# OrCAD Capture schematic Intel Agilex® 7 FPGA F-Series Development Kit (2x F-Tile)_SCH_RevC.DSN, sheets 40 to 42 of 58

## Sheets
40 PG43 INPUT POWER HSC: size C
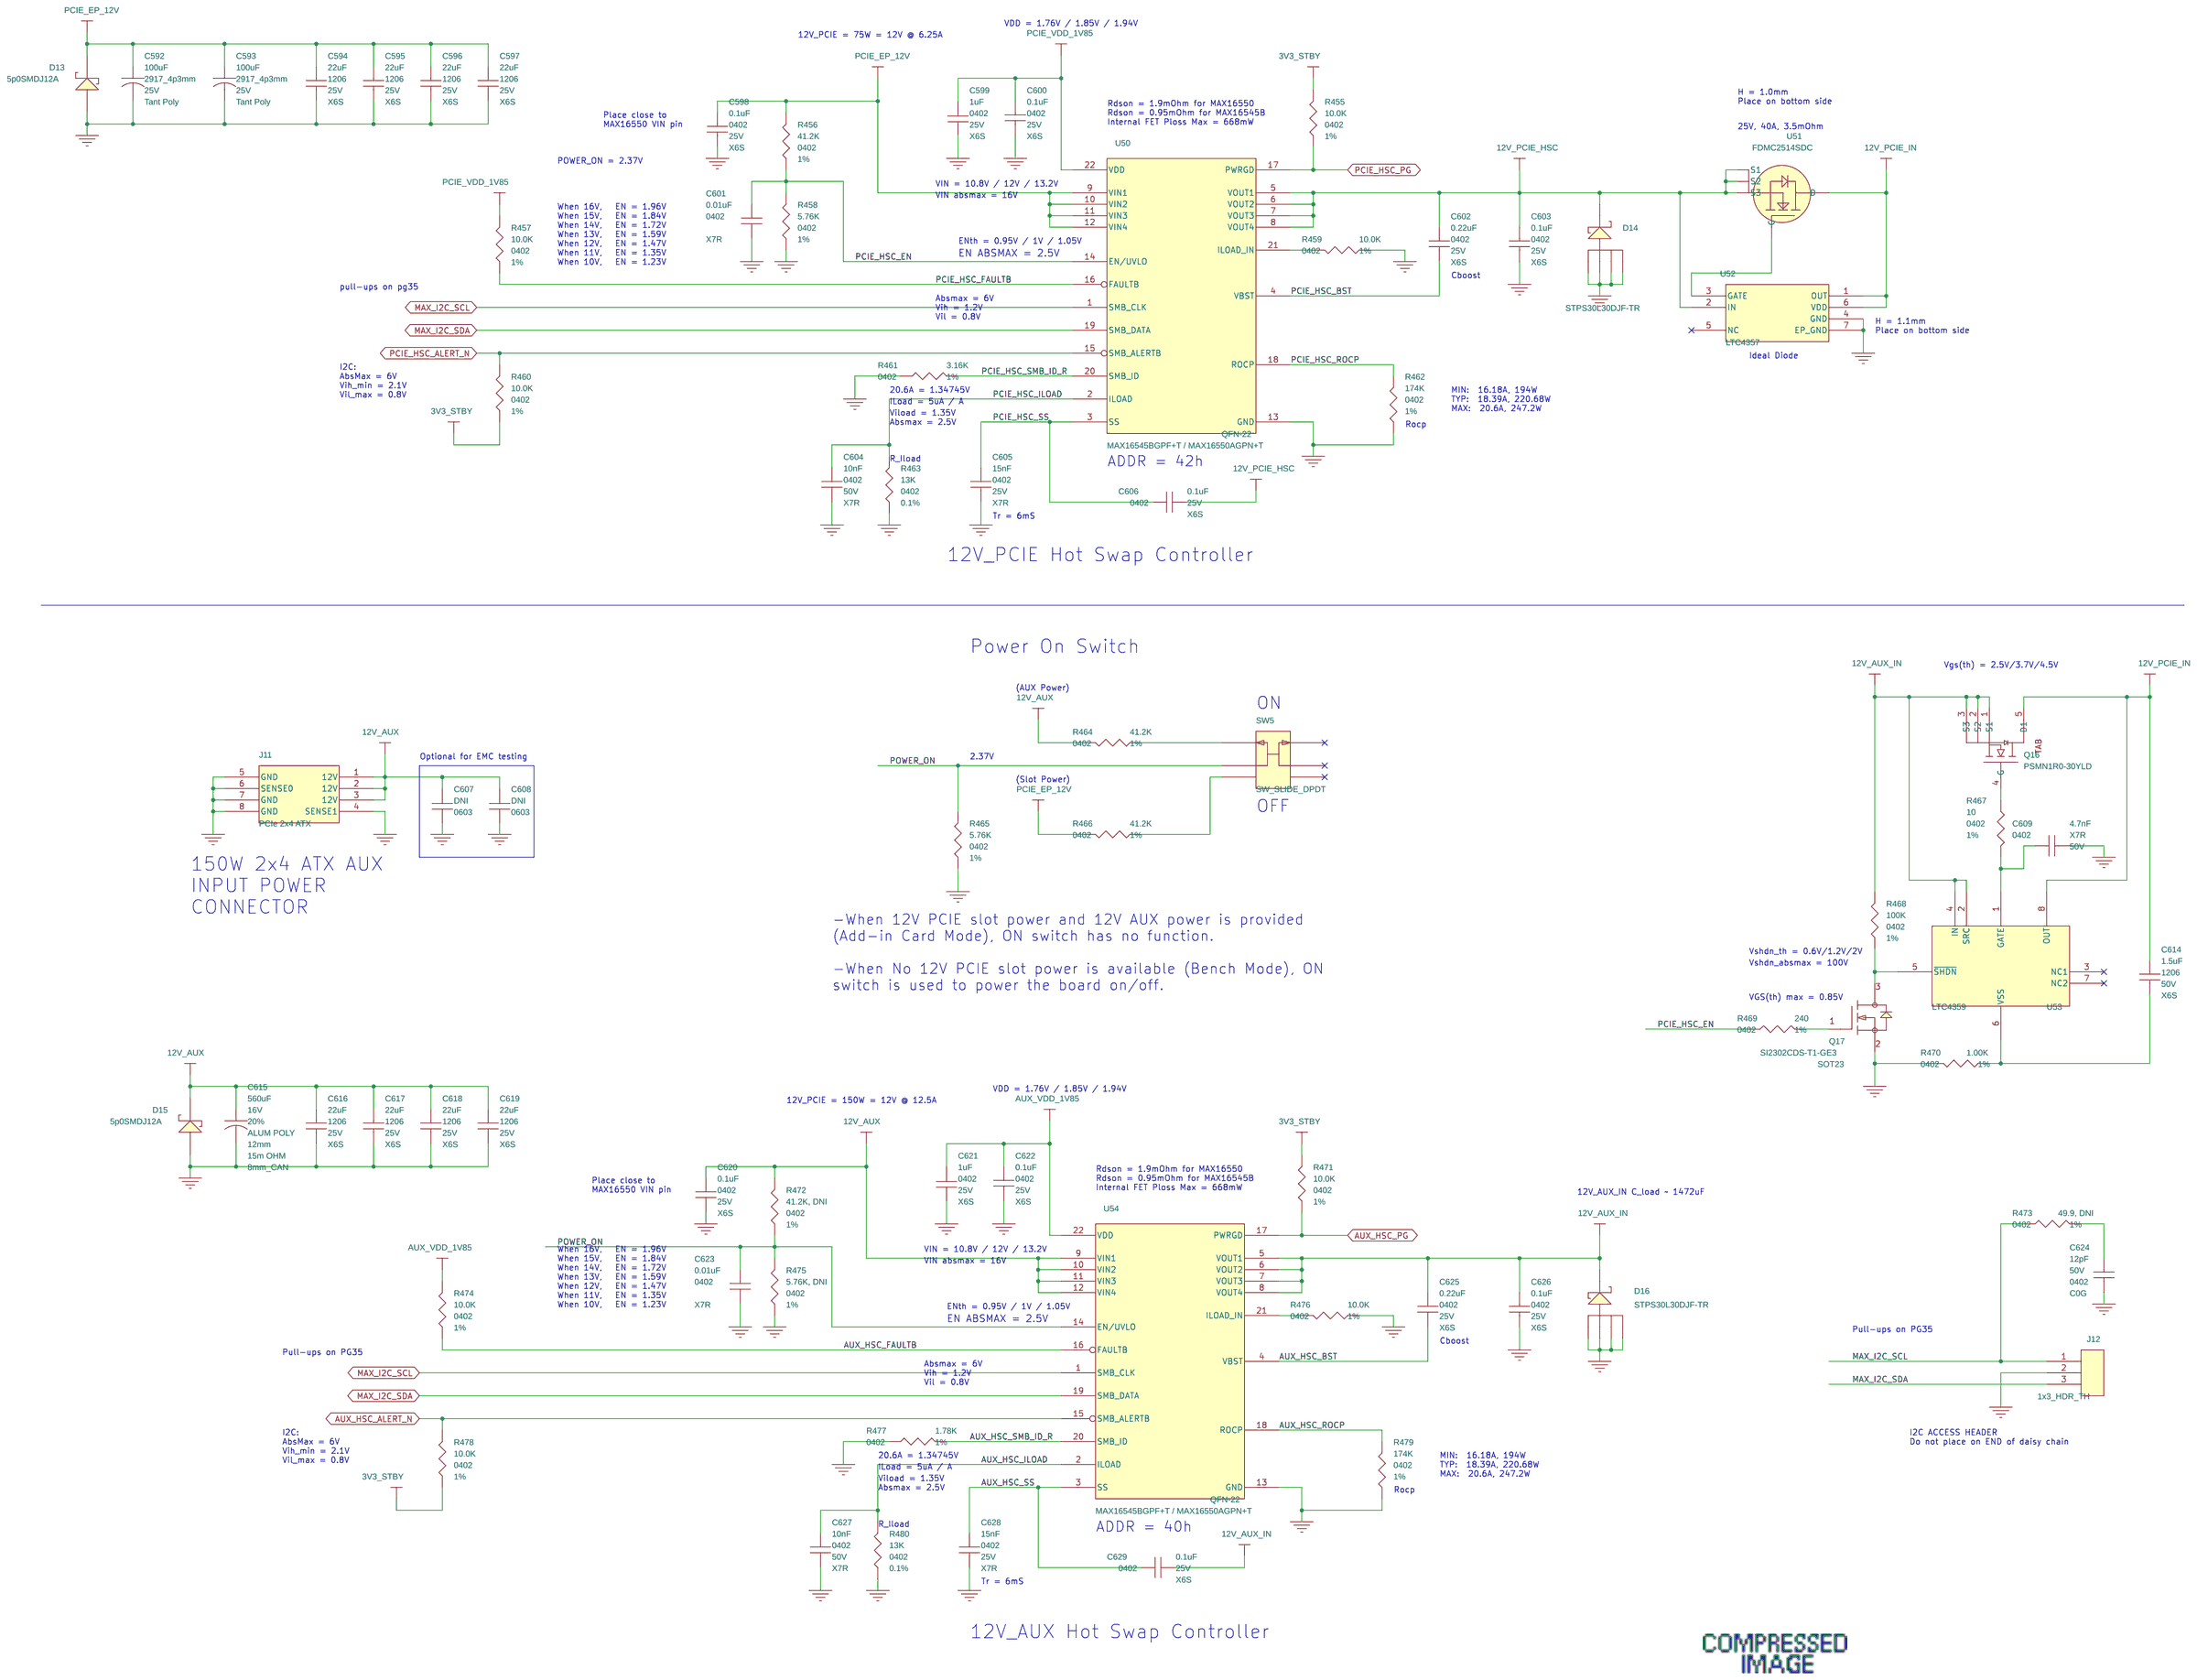
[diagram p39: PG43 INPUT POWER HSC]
41 PG45 3V3_STBY, 3V3_SYS: size C
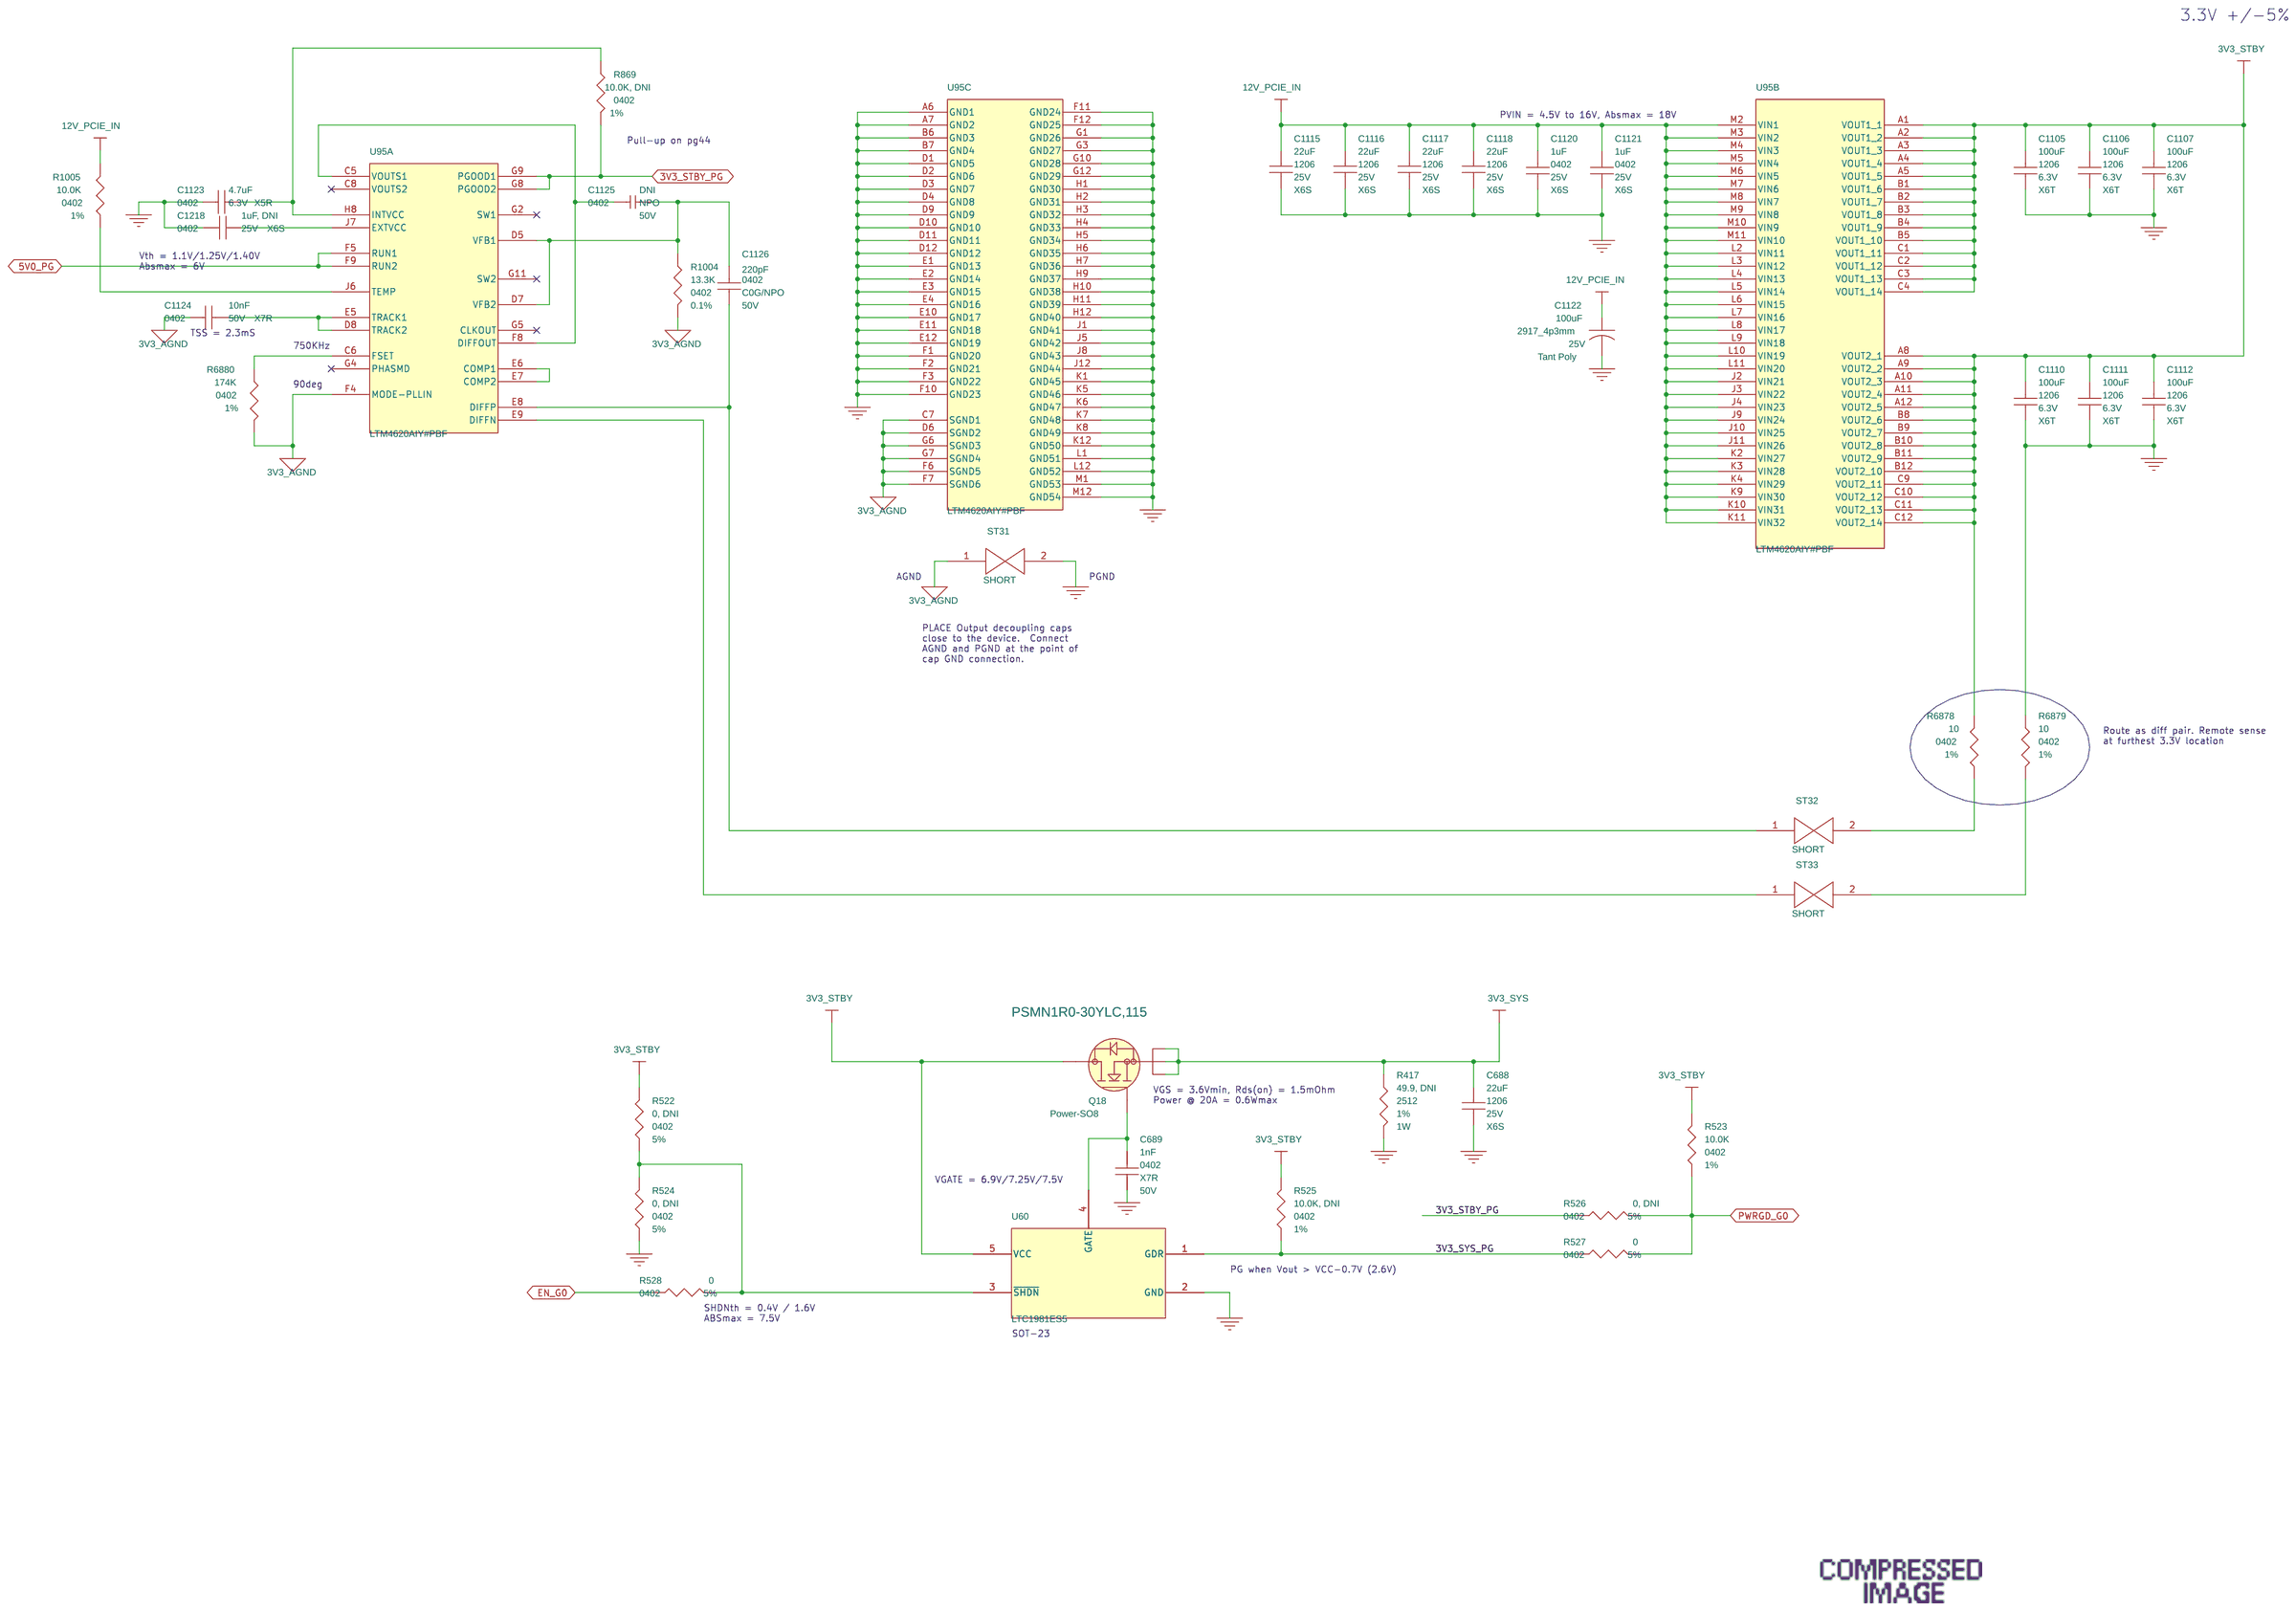
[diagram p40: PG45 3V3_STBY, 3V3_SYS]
42 PG46 VCC Controller: size C
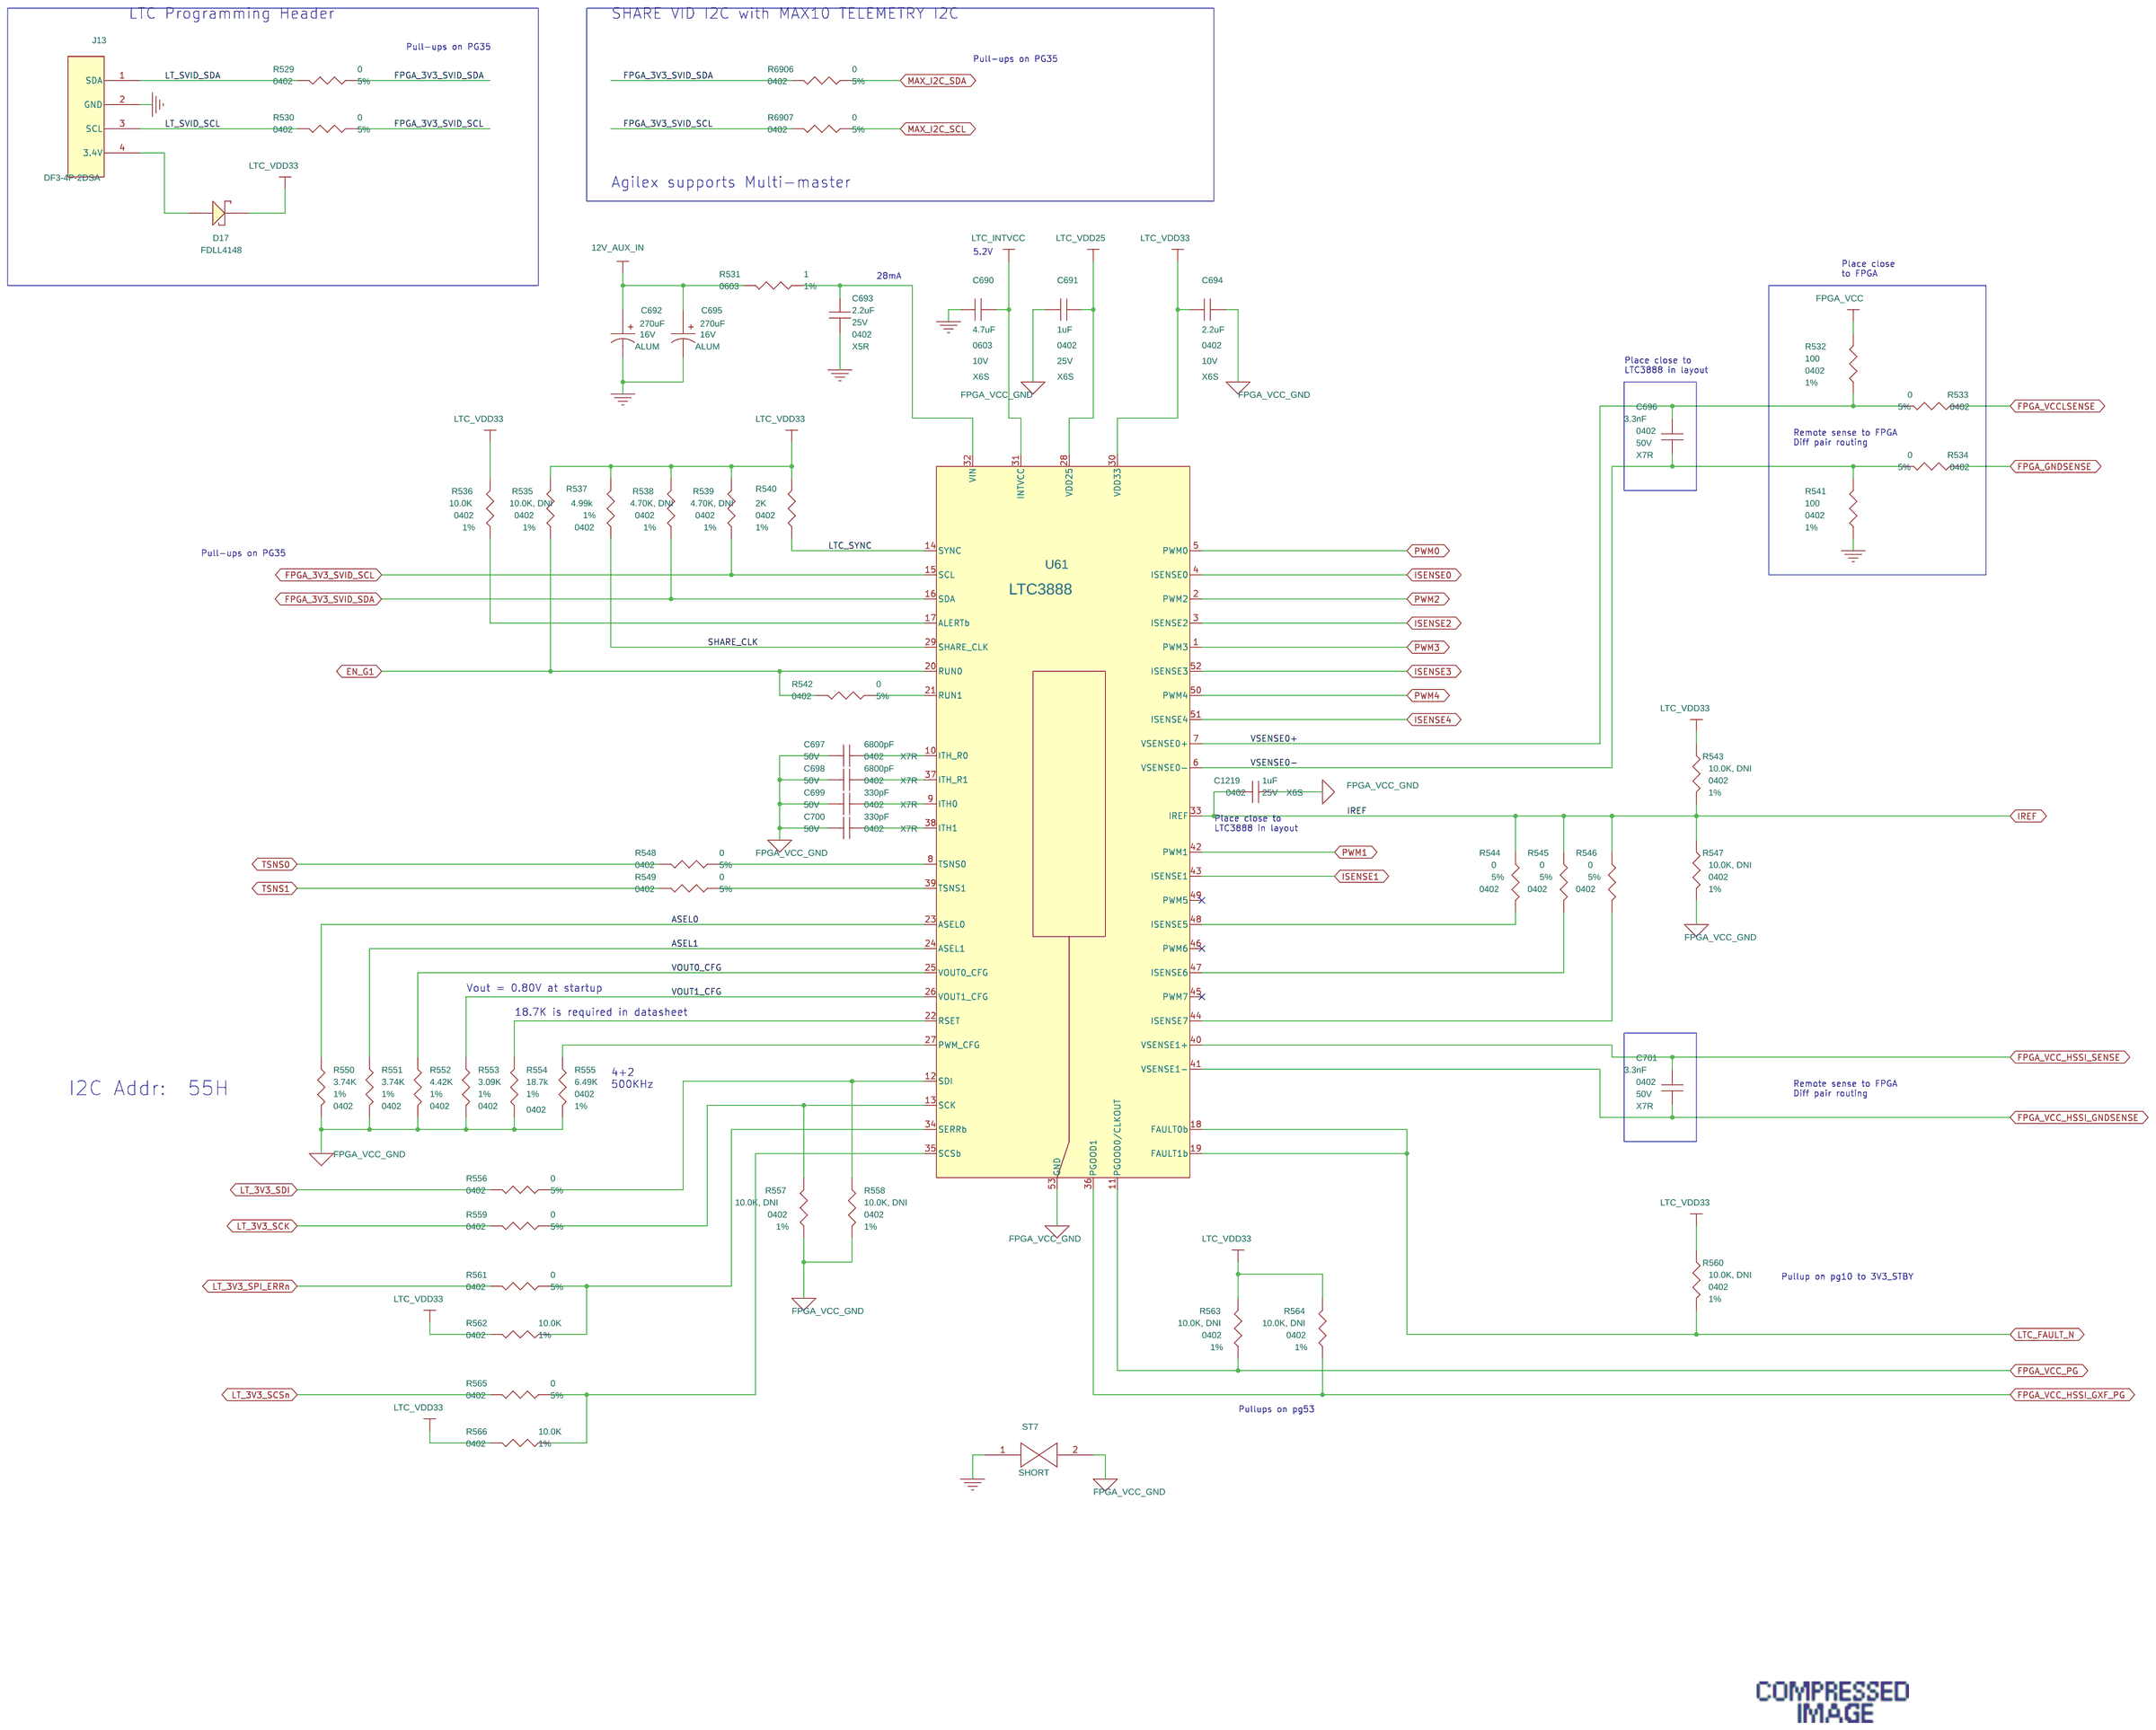
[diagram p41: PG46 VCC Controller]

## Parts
sheet PG43 INPUT POWER HSC
C592  100uF  [2917_4p3mm]
C593  100uF  [2917_4p3mm]
C594  22uF  [1206]
C595  22uF  [1206]
C596  22uF  [1206]
C597  22uF  [1206]
C598  0.1uF  [0402]
C599  1uF  [0402]
C600  0.1uF  [0402]
C601  0.01uF  [0402]
C602  0.22uF  [0402]
C603  0.1uF  [0402]
C604  10nF  [0402]
C605  15nF  [0402]
C606  0.1uF  [0402]
C607  DNI  [0603]
C608  DNI  [0603]
C609  4.7nF  [0402]
C614  1.5uF  [1206]
C615  560uF  [8mm_CAN]
C616  22uF  [1206]
C617  22uF  [1206]
C618  22uF  [1206]
C619  22uF  [1206]
C620  0.1uF  [0402]
C621  1uF  [0402]
C622  0.1uF  [0402]
C623  0.01uF  [0402]
C624  12pF  [0402]
C625  0.22uF  [0402]
C626  0.1uF  [0402]
C627  10nF  [0402]
C628  15nF  [0402]
C629  0.1uF  [0402]
D13  5p0SMDJ12A  [TVS_5p0SMDJ12A]
D14  STPS30L30DJF-TR  [PowerFLAT_5x6]
D15  5p0SMDJ12A  [TVS_5p0SMDJ12A]
D16  STPS30L30DJF-TR  [PowerFLAT_5x6]
J11  PCIe 2x4 ATX  [MOLEX_455860005]
J12  1x3_HDR_TH  [1x3_HDR_TH]
Q16  PSMN1R0-30YLD  [NFET_PSMN1R0-30YLD]
Q17  SI2302CDS-T1-GE3  [SOT23]
R455  10.0K  [0402]
R456  41.2K  [0402]
R457  10.0K  [0402]
R458  5.76K  [0402]
R459  10.0K  [0402]
R460  10.0K  [0402]
R461  3.16K  [0402]
R462  174K  [0402]
R463  13K  [0402]
R464  41.2K  [0402]
R465  5.76K  [0402]
R466  41.2K  [0402]
R467  10  [0402]
R468  100K  [0402]
R469  240  [0402]
R470  1.00K  [0402]
R471  10.0K  [0402]
R472  41.2K, DNI  [0402]
R473  49.9, DNI  [0402]
R474  10.0K  [0402]
R475  5.76K, DNI  [0402]
R476  10.0K  [0402]
R477  1.78K  [0402]
R478  10.0K  [0402]
R479  174K  [0402]
R480  13K  [0402]
SW5  SW_SLIDE_DPDT  [EG2207]
U50  MAX16545BGPF+T / MAX16550AGPN+T  [QFN-22]
U51  FDMC2514SDC  [FDMC8878_VER2]
U52  LTC4357  [dfn6_epad]
U53  LTC4359  [MSOP-8]
U54  MAX16545BGPF+T / MAX16550AGPN+T  [QFN-22]
sheet PG45 3V3_STBY, 3V3_SYS
C688  22uF  [1206]
C689  1nF  [0402]
C1105  100uF  [1206]
C1106  100uF  [1206]
C1107  100uF  [1206]
C1110  100uF  [1206]
C1111  100uF  [1206]
C1112  100uF  [1206]
C1115  22uF  [1206]
C1116  22uF  [1206]
C1117  22uF  [1206]
C1118  22uF  [1206]
C1120  1uF  [0402]
C1121  1uF  [0402]
C1122  100uF  [2917_4p3mm]
C1123  4.7uF  [0402]
C1124  10nF  [0402]
C1125  DNI  [0402]
C1126  220pF  [0402]
C1218  1uF, DNI  [0402]
Q18  PSMN1R0-30YLC,115  [Power-SO8]
R417  49.9, DNI  [2512]
R522  0, DNI  [0402]
R523  10.0K  [0402]
R524  0, DNI  [0402]
R525  10.0K, DNI  [0402]
R526  0, DNI  [0402]
R527  0  [0402]
R528  0  [0402]
R869  10.0K, DNI  [0402]
R1004  13.3K  [0402]
R1005  10.0K  [0402]
R6878  10  [0402]
R6879  10  [0402]
R6880  174K  [0402]
ST31  SHORT  [SHORT]
ST32  SHORT  [SHORT]
ST33  SHORT  [SHORT]
U60  LTC1981ES5  [LTC1981ES5_SOT23]
U95  LTM4620AIY#PBF  [BGA-144_REVERSE]  (sections A,B,C)
sheet PG46 VCC Controller
C690  4.7uF  [0603]
C691  1uF  [0402]
C692  270uF  [PANASONIC_SVPC_8X12]
C693  2.2uF  [0402]
C694  2.2uF  [0402]
C695  270uF  [PANASONIC_SVPC_8X12]
C696  3.3nF  [0402]
C697  6800pF  [0402]
C698  6800pF  [0402]
C699  330pF  [0402]
C700  330pF  [0402]
C701  3.3nF  [0402]
C1219  1uF  [0402]
D17  FDLL4148  [SOD-80]
J13  DF3-4P-2DSA  [DF3-4P-2DSA_01]
R529  0  [0402]
R530  0  [0402]
R531  1  [0603]
R532  100  [0402]
R533  0  [0402]
R534  0  [0402]
R535  10.0K, DNI  [0402]
R536  10.0K  [0402]
R537  4.99k  [0402]
R538  4.70K, DNI  [0402]
R539  4.70K, DNI  [0402]
R540  2K  [0402]
R541  100  [0402]
R542  0  [0402]
R543  10.0K, DNI  [0402]
R544  0  [0402]
R545  0  [0402]
R546  0  [0402]
R547  10.0K, DNI  [0402]
R548  0  [0402]
R549  0  [0402]
R550  3.74K  [0402]
R551  3.74K  [0402]
R552  4.42K  [0402]
R553  3.09K  [0402]
R554  18.7k  [0402]
R555  6.49K  [0402]
R556  0  [0402]
R557  10.0K, DNI  [0402]
R558  10.0K, DNI  [0402]
R559  0  [0402]
R560  10.0K, DNI  [0402]
R561  0  [0402]
R562  10.0K  [0402]
R563  10.0K, DNI  [0402]
R564  10.0K, DNI  [0402]
R565  0  [0402]
R566  10.0K  [0402]
R6906  0  [0402]
R6907  0  [0402]
ST7  SHORT  [SHORT]
U61  LTC3888  [LTC-UHG-52-1550]

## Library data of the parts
C592 C593 C1122 = PCAP: CAP TANTALUM 100UF 25V 2917; AGILE_LINK: http://sj-agile9app/Agile/PLMServlet?action=OpenEmailObject&classid=10000&objid=257237054; Item Num: H48376-001; LIFECYCLE_PHASE: Active; Lead Free Status: Lead Free; MFR_LIFECYCLE: Active; Manufacturer: Kemet; Manufacturer Part Num: T521X107M025ATE060; Num Pins: 2; PART_SUBCLASS: CAPACITORS; RATED_VOLTAGE: 25V; RoHS Compliant: RoHS Compliant; TOLERANCE: 20%; Type: Tant Poly
C594-C597 C616-C619 C688 C1115-C1118 = CAP: CAP CER 22UF 25V X6S 1206; AGILE_LINK: http://sj-agile9app/Agile/PLMServlet?action=OpenEmailObject&classid=10000&objid=257560276; Item Num: H65936-001; LIFECYCLE_PHASE: Active; Lead Free Status: Lead Free; MFR_LIFECYCLE: Active; Manufacturer: Murata; Manufacturer Part Num: GRM31CC81E226KE11L; Num Pins: 2; PART_SUBCLASS: CAPACITORS; RATED_VOLTAGE: 25V; RoHS Compliant: RoHS Compliant; TOLERANCE: 10%; Thermal Coefficient: X6S
C598 C600 C603 C606 C620 C622 C626 C629 = CAP: CAP CER 0.1UF 25V X6S 0402; Dielectric: X6S; IPN: K19434-001; Item Num: K19434-001; LIFECYCLE_PHASE: Active; Lead Free Status: Lead Free; MFR_LIFECYCLE: Active; Manufacturer: Murata; Manufacturer Part Num: GRM155C81E104KA12D; Num Pins: 2; PART_SUBCLASS: CAPACITORS; Part Class: CAPACITORS; RATED_VOLTAGE: 25V; RoHS Compliant: RoHS Compliant; Temperature Coefficient: X6S; Tolerance: 10%
C599 C621 C691 C1120 C1121 C1218 C1219 = CAP: CAP CER 1UF 25V X6S 0402; Item Num: H81594-001; Lead Free Status: Yes; Manufacturer: Murata; Manufacturer Part Num: GRM155C81E105KE11D; Num Pins: 2; Part Class: CAPACITORS; RATED_VOLTAGE: 25V; RoHS Compliant: Yes; Temperature Coefficient: X6S
C601 C623 = CAP: CAP, CER .01UF 16V X7R 0402; Item Num: A36096-008; Lead Free Status: Yes; Manufacturer: Murata; Manufacturer Part Num: GRM155R71E103KA01D; Manufacturer's Part No.: GRM155R71C103KA01D; Num Pins: 2; Part Class: CAPACITORS; RoHS Compliant: Yes; TOLERANCE: 10%; Temperature Coefficient: X7R; Voltage: 16V
C602 C625 = CAP: CAP CER 0.22UF 25V X6S 0402; CAPACITANCE: 0.1uF; Dielectric: X6S; Item Num: K19428-001; LIFECYCLE_PHASE: Active; Lead Free Status: Lead Free; Manufacturer: Murata; Manufacturer Part Num: GRT155C81E224KE01D; Num Pins: 2; Part Class: CAPACITORS; RATED_VOLTAGE: 25V; RoHS Compliant: RoHS Compliant; Tolerance: 10%
C604 C627 = CAP: CAP - CER, 10NF, 50V, +/-10%, X7R, 0402 SMD; Dielectric: X7R; Item Num: H61346-001; LIFECYCLE_PHASE: Active; Lead Free Status: Lead Free; Manufacturer: Murata; Manufacturer Part Num: GRM155R71H103KA88D; Num Pins: 2; Part Class: CAPACITORS; RATED_VOLTAGE: 50V; RoHS Compliant: RoHS Compliant; Temperature Coefficient: X7R; Tolerance: 10%; Voltage: 50V
C605 C628 = CAP: CAP CER 0.015UF 25V X7R 0402; CAPACITANCE: 0.015uF; Dielectric: X7R; Item Num: K28300-001; LIFECYCLE_PHASE: Active; Lead Free Status: Lead Free; Manufacturer: Murata; Manufacturer Part Num: GRM155R71E153KA61D; Num Pins: 2; Part Class: CAPACITORS; RATED_VOLTAGE: 25V; RoHS Compliant: RoHS Compliant; Tolerance: 10%
C607 C608 = CAP: DNI Place Holder; AGILE_LINK: http://sj-agile9app/Agile/PLMServlet?action=OpenEmailObject&classid=10000&objid=257560276; Item Num: XXXXXX-XXX; LIFECYCLE_PHASE: Active; Lead Free Status: Not Lead Free; MFR_LIFECYCLE: Active; Num Pins: 2; PART_SUBCLASS: CAPACITORS; RoHS Compliant: RoHS Compliant
C609 = CAP: CAP - CER 4700PF 50V 10% X7R 0402; AGILE_LINK: http://sj-agile9app/Agile/PLMServlet?action=OpenEmailObject&classid=10000&objid=256989767; Item Num: G24897-001; LIFECYCLE_PHASE: Active; Lead Free Status: Lead Free; MFR_LIFECYCLE: Active; Manufacturer: Murata; Manufacturer Part Num: GRM155R71H472KA01D; Num Pins: 2; PACKAGING: Tape & Reel (TR); PART_SUBCLASS: CAPACITORS; RATED_VOLTAGE: 50V; RoHS Compliant: RoHS Compliant; Supplier Part Num: GRM155R71H472KA01D; TOLERANCE: 10%; Temperature Coefficient: X7R
C614 = CAP: CAP CER 1.5UF 50V X6S 1206; Dielectric: X6S; Item Num: K19472-001; LIFECYCLE_PHASE: Active; Lead Free Status: Lead Free; Manufacturer: Murata; Manufacturer Part Num: GRT31CC81H155KE01L; Num Pins: 2; Part Class: CAPACITORS; RATED_VOLTAGE: 50V; RoHS Compliant: RoHS Compliant; Tolerance: 10%
C615 = PCAP: 560µF ±20% 16V Aluminum Polymer Capacitor Radial, Can - SMD 14 mOhm 5000 Hrs @ 105°C; AGILE_LINK: http://sj-agile9app/Agile/PLMServlet?action=OpenEmailObject&classid=10000&objid=257237054; ESR: 15m OHM; Height: 12mm; Item Num: K22159-001; LIFECYCLE_PHASE: Active; Lead Free Status: Lead Free; MFR_LIFECYCLE: Active; Manufacturer: Panasonic; Manufacturer Part Num: 16SVPF560M; Num Pins: 2; PART_SUBCLASS: CAPACITORS; RATED_VOLTAGE: 16V; RoHS Compliant: RoHS Compliant; TOLERANCE: 20%; TYPE: ALUM POLY
C624 = CAP: CAPC,C0G,0402,12.000PF,50.000V,+/- 5%; AGILE_LINK: http://sj-agile9app/Agile/PLMServlet?action=OpenEmailObject&classid=10000&objid=257385742; Item Num: A36095-043; LIFECYCLE_PHASE: Active; Lead Free Status: Lead Free; MFR_LIFECYCLE: Active; Manufacturer: Murata; Manufacturer Part Num: GRM1555C1H120JA01F; Num Pins: 2; PART_SUBCLASS: CAPACITORS; RATED_VOLTAGE: 50V; RoHS Compliant: RoHS Compliant; TOLERANCE: +/-5%; Temperature Coefficient: C0G
D13 D15 = TVS_5p0SMDJ12A: TVS DIODE 12VWM 19.9VC SMD; Item Num: J31279-001; Manufacturer: Littelfuse Inc.; Manufacturer Part Num: 5.0SMDJ12A
D14 D16 = STPS30L30DJF-TR: DIODE SCHOTTKY 30V 30A POWERFLAT; Item Num: K21430-001; Manufacturer: STMicroelectronics
J11 = 2X4_PCIE_ATX_1: CONN - PCIE ATX, 8POS HEADER, 4.2MM, R/A; Item Num: K11298-001; Manufacturer: Molex; Manufacturer Part Num: 45586-0005
J12 = 1x3_HDR_TH: CONN HEADER 3POS .100" T/H GOLD; Item Num: K21525-001; Manufacturer: Samtec; Manufacturer Part Num: HTSW-103-07-L-S
Q16 = PSMN1R0-30YLD_0: MOSFET, N-Channel, 30V, 1mOhm, 300A; Item Num: K21466-001; Manufacturer: Nexperia USA Inc.
Q17 = PWRMOSFET_EN_GSD_1: IC, MOSFET, N-Channel, 20V; Item Num: K69552-001; Manufacturer: Vishay Siliconix
R455 R457 R459 R460 R471 R474 R476 R478 R523 R536 R562 R566 R1005 = RESISTOR: RES,10.0K OHMS,1.0%,1/16W, 0402; AGILE_LINK: http://sj-agile9app/Agile/PLMServlet?action=OpenEmailObject&classid=10000&objid=146548997; Item Num: K28115-001; LIFECYCLE_PHASE: Active; Lead Free Status: Yes; MFR_LIFECYCLE: Active; Manufacturer: Panasonic; Manufacturer Part Num: ERJ-2RKF1002X; Num Pins: 2; PART_SUBCLASS: RESISTORS; POWER: 1/16W; RoHS Compliant: Yes; TOLERANCE: 1%
R456 R464 R466 = RESISTOR: RES SMD 41.2K OHM 1% 1/10W 0402; AGILE_LINK: http://sj-agile9app/Agile/PLMServlet?action=OpenEmailObject&classid=10000&objid=146548997; Item Num: K16280-001; LIFECYCLE_PHASE: Active; Lead Free Status: Yes; MFR_LIFECYCLE: Active; Manufacturer: Panasonic; Manufacturer Part Num: ERJ-2RKF4122X; Num Pins: 2; PART_SUBCLASS: RESISTORS; POWER: 1/10W; RoHS Compliant: Yes; TOLERANCE: 1%
R458 R465 = RESISTOR: RES SMD 5.76K OHM 1% 1/10W 0402; AGILE_LINK: http://sj-agile9app/Agile/PLMServlet?action=OpenEmailObject&classid=10000&objid=146548997; Item Num: K15735-001; LIFECYCLE_PHASE: Active; Lead Free Status: No; MFR_LIFECYCLE: Active; Manufacturer: Panasonic; Manufacturer Part Num: ERJ-2RKF5761X; Num Pins: 2; PART_SUBCLASS: RESISTORS; POWER: 1/10W; RoHS Compliant: Yes; TOLERANCE: 1%
R461 = RESISTOR: RES SMD 3.16K OHM 1% 1/10W 0402; Item Num: C59243-001; Manufacturer: Panasonic; Manufacturer Part Num: ERJ-2RKF3161X; TOLERANCE: 1%
R462 R479 R6880 = RESISTOR: RES SMD 174K OHM 1% 1/10W 0402; Item Num: A93548-222; Manufacturer: Vishay; Manufacturer Part Num: CRCW0402174KFKED; TOLERANCE: 1%
R463 R480 = RESISTOR: RES SMD 13K OHM 0.1% 1/16W 0402; AGILE_LINK: http://sj-agile9app/Agile/PLMServlet?action=OpenEmailObject&classid=10000&objid=146548997; Item Num: K21641-001; LIFECYCLE_PHASE: Active; Lead Free Status: Yes; MFR_LIFECYCLE: Active; Manufacturer: Panasonic; Manufacturer Part Num: ERA-2AEB133X; Num Pins: 2; PART_SUBCLASS: RESISTORS; POWER: 1/16W; RoHS Compliant: Yes; TOLERANCE: 0.1%
R467 = RESISTOR: RES, 10 OHM, 1%, 1/16W, 0402; AGILE_LINK: http://sj-agile9app/Agile/PLMServlet?action=OpenEmailObject&classid=10000&objid=146932246; Item Num: A80345-001; LIFECYCLE_PHASE: Active; Lead Free Status: Yes; Manufacturer: Panasonic; Manufacturer Part Num: ERJ-2RKF10R0X; Num Pins: 2; PART_SUBCLASS: RESISTORS; POWER: 1/16W; Part Class: Resistors; RoHS Compliant: Yes; TOLERANCE: 1%
R468 = RESISTOR: RES,100K OHMS,1.0%,1/16W,0402; Item Num: A78422-001; Lead Free Status: Yes; Manufacturer: Panasonic; Manufacturer Part Num: ERJ-2RKF1003X; Num Pins: 2; Part Class: Resistors; RoHS Compliant: Yes; TOLERANCE: 1%
R469 = RESISTOR: RES - 240 OHM, 1/16W, 1%, 0402 SMD; Item Num: K15783-001; LIFECYCLE_PHASE: Active; Lead Free Status: Yes; MFR_LIFECYCLE: Active; Manufacturer: Panasonic; Manufacturer Part Num: ERJ-2RKF2400X; Num Pins: 2; PART_SUBCLASS: RESISTORS; RoHS Compliant: Yes; Tolerance: 1%
R470 = RESISTOR: RES,1.00K OHMS,1.0%,1/16W,0402; Item Num: G60609-021; Lead Free Status: Yes; Manufacturer: Panasonic; Manufacturer Part Num: ERJ-2RKF1001X; Num Pins: 2; Part Class: Resistors; TOLERANCE: 1%
R472 = RESISTOR: RES SMD 41.2K OHM 1% 1/10W 0402; AGILE_LINK: http://sj-agile9app/Agile/PLMServlet?action=OpenEmailObject&classid=10000&objid=146548997; Item Num: K16280-001; LIFECYCLE_PHASE: Active; Lead Free Status: Yes; MFR_LIFECYCLE: Active; Manufacturer: Panasonic; Manufacturer Part Num: ERJ-2RKF4122X; Num Pins: 2; PART_SUBCLASS: RESISTORS; POWER: 1/10W; RESISTANCE: 41.2K; RoHS Compliant: Yes; TOLERANCE: 1%
R473 = RESISTOR: RES SMD 49.9 OHM 1% 1/10W 0402; Item Num: K16545-001; LIFECYCLE_PHASE: Active; Lead Free Status: Yes; MFR_LIFECYCLE: Active; Manufacturer: NIC Components Corp.; Manufacturer Part Num: NRC04F49R9TRF; Num Pins: 2; PART_SUBCLASS: RESISTORS; POWER: 1/16W; Part Class: Resistors; RESISTANCE: 49.9; RoHS Compliant: Yes; Tolerance: 1%
R475 = RESISTOR: RES SMD 5.76K OHM 1% 1/10W 0402; AGILE_LINK: http://sj-agile9app/Agile/PLMServlet?action=OpenEmailObject&classid=10000&objid=146548997; Item Num: K15735-001; LIFECYCLE_PHASE: Active; Lead Free Status: No; MFR_LIFECYCLE: Active; Manufacturer: Panasonic; Manufacturer Part Num: ERJ-2RKF5761X; Num Pins: 2; PART_SUBCLASS: RESISTORS; POWER: 1/10W; RESISTANCE: 5.76K; RoHS Compliant: Yes; TOLERANCE: 1%
R477 = RESISTOR: RES - 1.78K OHM, 1/16W, 1%, 0402 SMD; Item Num: K15755-001; Manufacturer: Vishay; Manufacturer Part Num: CRCW04021K78FKxx; TOLERANCE: 1%
SW5 = SW_SLIDE_DPDT: SWITCH - SLIDE DPDT, 30V, 0.2AMP, Vertical; Item Num: J42686-001; Manufacturer: E-SWITCH
U50 U54 = MAX16545B: IC, Circuit Breaker Protection with Current Sense and PMBUS; Item Num: K21748-001; Manufacturer: Maxim; Manufacturer Part Num: MAX16545BGPF+T
U51 = FDMC8878_VER2: MOSFET N-CHANNEL DUAL COOL PWR TRENCH 40A 25V 3.5mOHM; Item Num: K14521-001; Manufacturer: Fairchild Semiconductor
U52 = LTC4357: IC - POSITIVE HIGH VOLTAGE IDEAL DIODE CONTROLLER, VIN 9V-80V, 6-LEAD DFN; AGILE_LINK: http://sj-agile9app/Agile/PLMServlet?action=OpenEmailObject&classid=10000&objid=259478351; Item Num: K64810-001; LIFECYCLE_PHASE: Preliminary; Lead Free Status: Lead Free; MFR_LIFECYCLE: Active; Manufacturer: Linear Technology; Manufacturer Part Num: LTC4357IDCB#xxxPBF; Num Pins: 7; PART_SUBCLASS: ICS; RoHS Compliant: RoHS Compliant
U53 = LTC4359: IC - Ideal Diode Controller with Reverse Input Protection; Item Num: K22140-001; Manufacturer: Linear Technology; Manufacturer Part Num: LTC4359IMS8#PBF
C689 = Cap_10000PF_50V_0402: CAP CER 1000PF 50V X7R 0402; Item Num: C20831-001; Manufacturer: Panasonic; Manufacturer Part Num: ECJ-0EB1H102K; Temp Coefficient: X7R; Working Voltage: 50V
C1105-C1107 C1110-C1112 = CAP: CAP CER 100UF 6.3V X6T 1206; Dielectric Type: X6T; Item Num: H65271-004; LIFECYCLE_PHASE: Active; Lead Free Status: Lead Free; MFR_LIFECYCLE: Active; Manufacturer: Murata; Manufacturer PN: GRM31CD80J107ME39L; Manufacturer Part Num: GRM31CD80J107ME39L; Num Pins: 2; PART_SUBCLASS: CAPACITORS; RATED_VOLTAGE: 6.3V; Rated Voltage: 6.3V; RoHS Compliant: RoHS Compliant; TOLERANCE: 20%; Temperature Coefficient: X6T; Working Voltage: 6.3V
C1123 = CAP: CAP - CER 4.7UF, +/-20%, 6.3V, X5R, 0402; IPN: A36096-107; Item Num: A36096-107; Manufacturer: Murata; Manufacturer Part Num: GRM155R60J475ME87D; Temperature Coefficient: X5R; Tolerance: +/-20%; Voltage: 6.3V
C1124 = Cap_10000PF_50V_0402: CAP - CER, 10NF, 50V, +/-10%, X7R, 0402 SMD; Dielectric: X7R; Item Num: H61346-001; LIFECYCLE_PHASE: Active; Lead Free Status: Lead Free; Manufacturer Part Num: GRM155R71H103KA88D; Num Pins: 2; Part Class: CAPACITORS; RATED_VOLTAGE: 50V; RoHS Compliant: RoHS Compliant; Temperature Coefficient: X7R; Tolerance: 10%; Voltage: 50V
C1125 = Cap,_NP,_0402: CAP, CERAMIC, 100pF, 0402, 5%, 50VDC, NPO; Item Num: K13768-001; Manufacturer: Murata; Manufacturer Part Num: GRM1555C1H101JA01D; Temperature Coefficient: NPO; Voltage: 50V
C1126 = CAP: CAP - CERAMIC, 220PF, 5%, 50V, 0402, C0G/NPO; Dielectric: C0G/NPO; Item Num: D32090-001; Lead Free Status: Yes; Manufacturer: Kemet; Manufacturer Part Num: C0402C221J5GACTU; Manufacturer's Part No.: C0402C221J5GACTU; Num Pins: 2; Part Class: CAPACITORS; Price: 0.07; RoHS Compliant: Yes; Tolerance: 5%; Voltage: 50V
Q18 = MOSFET_N-DIODE-A-SO8_1: MOSFET N-CH 30V 100A LFPAK; COMPFIXED: NXP; COMPGROUP: PSMN1R030YLC; Item Num: K21467-001; Manufacturer: NXP; Manufacturer Part Num: PSMN1R030YLC,115
R417 = RESISTOR: RES SMD 49.9 OHM 1% 1W 2512; Item Num: E58025-001; Lead Free Status: No; Manufacturer: Vishay-Dale; Manufacturer Part Num: RMCF2512FT49R9; Num Pins: 2; Part Class: RESISTORS; Power: 1W; Price: 0; RoHS Compliant: Yes; Tolerance: 1%
R522 R524 R526 = RESISTOR: RES ZERO OHM 1/16W 5% 0402 SMD; IPN: A93549-001; Item Num: A93549-001; Lead Free Status: Yes; Manufacturer: Yageo; Manufacturer Part Num: RC0402JR-070RL; Num Pins: 2; Part Class: RESISTORS; RoHS Compliant: Yes; Tolerance: 5%
R525 R535 R543 R547 R557 R558 R560 R563 R564 R869 = RESISTOR: RES,10.0K OHMS,1.0%,1/16W, 0402; AGILE_LINK: http://sj-agile9app/Agile/PLMServlet?action=OpenEmailObject&classid=10000&objid=146548997; Item Num: K28115-001; LIFECYCLE_PHASE: Active; Lead Free Status: Yes; MFR_LIFECYCLE: Active; Manufacturer: Panasonic; Manufacturer Part Num: ERJ-2RKF1002X; Num Pins: 2; PART_SUBCLASS: RESISTORS; POWER: 1/16W; RESISTANCE: 10.0K; RoHS Compliant: Yes; TOLERANCE: 1%
R527-R530 R533 R534 R542 R544-R546 R548 R549 R556 R559 R561 R565 R6906 R6907 = RESISTOR: RES ZERO OHM 1/16W 5% 0402 SMD; Item Num: A93549-001; Lead Free Status: No; Manufacturer: Yageo; Manufacturer Part Num: RC0402JR-070RL; Num Pins: 2; Part Class: RESISTORS; RoHS Compliant: Yes; Tolerance: 5%
R1004 = RESISTOR: RES - 13.3K OHM, 1/16W, 0.1%, 0402 SMD; AGILE_LINK: http://sj-agile9app/Agile/PLMServlet?action=OpenEmailObject&classid=10000&objid=146753272; Item Num: C79651-098; LIFECYCLE_PHASE: Active; Lead Free Status: No; MFR_LIFECYCLE: Active; Manufacturer: Yageo; Manufacturer Part Num: RT0402BRD0713K3L; Num Pins: 2; PART_SUBCLASS: RESISTORS; POWER: 1/16W; RoHS Compliant: Yes; TOLERANCE: 0.1%
R6878 R6879 = RESISTOR: RES, 10 OHM, 1%, 1/16W, 0402; Item Num: A80345-001; LIFECYCLE_PHASE: Active; Lead Free Status: Yes; Manufacturer: Panasonic; Manufacturer Part Num: ERJ-2RKF10R0X; Num Pins: 2; PART_SUBCLASS: RESISTORS; POWER: 1/16W; Part Class: Resistors; RoHS Compliant: Yes; TOLERANCE: 1%
ST7 ST31-ST33 = SHORT
U60 = LTC1981ES5: IC HI-SIDE SW CTRL SNGL TSOT23-5; Item Num: K22147-001; Manufacturer: Linear Technology; Manufacturer Part Num: LTC1981ES5#TRMPBF
U95 = LTM4620AIY#PBF: IC, LIN, BGA, LTM4620A, DC/DC Regulator; Item Num: M59339-001; Manufacturer: ADI
C690 = CAP: CAP CER 4.7UF 10V X6S 0603; AGILE_LINK: http://sj-agile9app/Agile/PLMServlet?action=OpenEmailObject&classid=10000&objid=242850622; Item Num: K19437-001; LIFECYCLE_PHASE: Active; MFR_LIFECYCLE: Active; Manufacturer: Murata; Manufacturer Part Num: GRM185C81A475KE11D; Num Pins: 2; PACKAGING: Tape & Reel (TR); PART_SUBCLASS: CAPACITORS; RATED_VOLTAGE: 10V; RoHS Compliant: RoHS Compliant; TOLERANCE: 10%; Temperature Coefficient: X6S
C692 C695 = CAP_P_ALT: CAP.,270uF,ALUM,16V,20%,SMD 8x11.9mm, E12; CLASS: DISCRETE; Component: cap; Dielectric Type: ALUM; IPN: xxxxxx-xxx; Item Num: A31228-055; Manufacturer: PANASONIC; Manufacturer PN: 16SVPC270M; Manufacturer Part Num: 16SVPC270M; PART_NUMBER: 150-3364; Package Size: SMD 8x11.9mm, E12; Rated Voltage: 16V; Tolerance: 20%
C693 = CAP: CAPC,X5R,0402,2.2UF,25.00V,+/- 10%; CLASS: DISCRETE; Dielectric Type: X5R; FPLIST: CC0805N,CC0805L,CC0805M; IPN: H87713-001; Item Num: H87713-001; Manufacturer: Murata; Manufacturer PN: GRM155R61E225KE11D; Manufacturer Part Num: GRM155R61E225KE11D; PART_NUMBER: 150-0578; Rated Voltage: 25V; Temperature Coefficient: X5R; Tolerance: 10%
C694 = CAP: CAP CER 2.2UF 10V X6S 0402; Dielectric: X6S; Item Num: H90637-001; LIFECYCLE_PHASE: Active; Lead Free Status: Lead Free; Manufacturer: Murata; Manufacturer Part Num: GRM155C81A225KE44D; Num Pins: 2; Part Class: CAPACITORS; RATED_VOLTAGE: 10V; RoHS Compliant: RoHS Compliant; Tolerance: 10%
C696 C701 = CAP: CAP, CERAMIC, 3300PF, 10%, 50V, X7R, 0402; Item Num: K13754-001; LIFECYCLE_PHASE: Active; Lead Free Status: Lead Free; MFR_LIFECYCLE: Active; Manufacturer: Murata; Manufacturer Part Num: GRM155F51H332ZA01x; Num Pins: 2; PART_SUBCLASS: CAPACITORS; RATED_VOLTAGE: 50V; RoHS Compliant: RoHS Compliant; TOLERANCE: +/-10%; Temperature Coefficient: X7R
C697 C698 = CAP: 6800pF ±10% 50V Ceramic Capacitor X7R 0402; CLASS: DISCRETE; Dielectric Type: X7R; IPN: xxxxxx-xxx; Item Num: A36096-117; Manufacturer: Yageo; Manufacturer PN: CC0402KRX7R9BB682; Manufacturer Part Num: CC0402KRX7R9BB682; Rated Voltage: 50V; Temperature Coefficient: X7R; Tolerance: 10%
C699 C700 = CAP: CAP CER 330PF 50V C0G/NP0 0402; CLASS: DISCRETE; Dielectric Type: X7R; Item Num: K13738-001; Manufacturer: Murata; Manufacturer Part Num: GRM1555C1H331JA01D; Rated Voltage: 50V; Tolerance: 10%
D17 = TVS_5p0SMDJ12A: DIODE GEN PURP 100V 200MA SOD80; Item Num: 200947-901; Manufacturer: Fairchild
J13 = DF3-4P-2DSA: CONN_HDR,4X1,PLG,VT,2.0000mm,9ST,BK; Item Num: M53332-001; Manufacturer: Hirose Electric; Manufacturer Part Num: DF3-4P-2DSA(01)
R531 = RES: RES.,1 OHM,1%,1/10W,0603; CLASS: DISCRETE; FPLIST: CR0603N,CR0603L,CR0603M; IPN: xxxxxx-xxx; Item Num: A93550-324; Manufacturer: YAGEO; Manufacturer PN: RC0603FR-071RL; Manufacturer Part Num: RC0603FR-071RL; PART_NUMBER: 100-0163; Rated Power: 1/10W; Temperature Coefficient: 200ppm/C; Tolerance: 1%
R532 R541 = RESISTOR: RES,100 OHMS,1.0%,1/16W,0402; Item Num: A36092-043; Lead Free Status: Yes; Manufacturer: Yageo; Manufacturer Part Num: RC0402FR-07100RL; Num Pins: 2; Part Class: Resistors; Price: 0; RoHS Compliant: Yes; Tolerance: 1%
R537 = RES: RES D,0402,4.99 kOHM,1.00%,1/16W; CLASS: DISCRETE; Item Num: A93548-202; Manufacturer: Vishay; Manufacturer PN: CRCW04024K99FKED; Manufacturer Part Num: CRCW04024K99FKED; Rated Power: 1/10W; Tolerance: 1%
R538 R539 = RESISTOR: RES,4.70K OHMS,1.0%,1/16W,0402; AGILE_LINK: http://sj-agile9app/Agile/PLMServlet?action=OpenEmailObject&classid=10000&objid=146753272; Item Num: A93548-517; LIFECYCLE_PHASE: Active; Lead Free Status: Yes; MFR_LIFECYCLE: Active; Manufacturer: Vishay; Manufacturer Part Num: CRCW04024K70FKED; Num Pins: 2; PART_SUBCLASS: RESISTORS; POWER: 1/16W; RESISTANCE: 4.7K; RoHS Compliant: Yes; TOLERANCE: 1%
R540 = RESISTOR: RES SMD 2K OHM 1% 1/16W 0402; Item Num: J43524-001; Lead Free Status: Yes; Manufacturer: Panasonic; Manufacturer Part Num: ERJ-2RKF2001X; Num Pins: 2; Part Class: RESISTORS; Power Rating: 1/16W; RoHS Compliant: Yes; Tolerance: 1%
R550 R551 = RES: RES D,0402,3.74 kOHM,1.00%,1/16W; CLASS: DISCRETE; IPN: xxxxxx-xxx; Item Num: A93548-025; Manufacturer: Vishay; Manufacturer PN: CRCW04023K74FKED; Manufacturer Part Num: CRCW04023K74FKED; Rated Power: 1/16W; Tolerance: 1%
R552 = RES: RES D,0402,4.42 kOHM,1.00%,1/16W; CLASS: DISCRETE; Item Num: K32804-001; Manufacturer: Yageo; Manufacturer Part Num: RC0402FR-074K42L; Rated Power: 1/16W; Tolerance: 1%
R553 = RES: RES D,0402,3.09 kOHM,1.00%,1/16W; CLASS: DISCRETE; IPN: xxxxxx-xxx; Item Num: A93548-410; Manufacturer: Yageo; Manufacturer Part Num: RC0402FR-073K09L; Rated Power: 1/16W; Tolerance: 1%
R554 = RES: RES SMD 18.7K OHM 1% 1/16W 0402; CLASS: DISCRETE; IPN: xxxxxx-xxx; Item Num: G21796-239; Manufacturer: YAGEO; Manufacturer PN: RC0402FR-0718K7P; Manufacturer Part Num: RC0402FR-0718K7P; Rated Power: 1/10W; Temperature Coefficient: +/-100; Tolerance: 1%
R555 = RES: RES D,0402,6.49 kOHM,1.00%,1/16W,YES; CLASS: DISCRETE; Item Num: A93548-267; Manufacturer: Yageo; Manufacturer Part Num: RC0402FR-076K49L; Rated Power: 1/16W; Tolerance: 1%
U61 = LTC3888-UHG: IC,8-Phase, Dual Output Synch. Buck Cvrtr.,QFN-52 (UHG); CLASS: IC; IPN: xxxxxx-xxx; Item Num: K82944-001; Manufacturer: LINEAR TECH.; Manufacturer PN: LTC3888EUHG#PBF; Manufacturer Part Num: LTC3888IUHG#PBF; PART_NUMBER: LTC3888EUHG#PBF; Package Type: QFN-52 (UHG)

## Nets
3V3_AGND: C1124.1 R1004.1 R6880.1 ST31.1 U95.C7(SGND1) U95.D6(SGND2) U95.F4(MODE-PLLIN) U95.F6(SGND5) U95.F7(SGND6) U95.G6(SGND3) U95.G7(SGND4)
3V3_STBY: C1105.2 C1106.2 C1107.2 C1110.2 C1111.2 C1112.2 Q18.MB R455.1 R460.2 R471.1 R478.2 R522.2 R523.1 R525.1 R6878.2 U60.5(VCC) U95.A1(VOUT1_1) U95.A2(VOUT1_2) U95.A3(VOUT1_3) U95.A4(VOUT1_4) U95.A5(VOUT1_5) U95.A8(VOUT2_1) U95.A9(VOUT2_2) U95.A10(VOUT2_3) U95.A11(VOUT2_4) U95.A12(VOUT2_5) U95.B1(VOUT1_6) U95.B2(VOUT1_7) U95.B3(VOUT1_8) U95.B4(VOUT1_9) U95.B5(VOUT1_10) U95.B8(VOUT2_6) U95.B9(VOUT2_7) U95.B10(VOUT2_8) U95.B11(VOUT2_9) U95.B12(VOUT2_10) U95.C1(VOUT1_11) U95.C2(VOUT1_12) U95.C3(VOUT1_13) U95.C4(VOUT1_14) U95.C9(VOUT2_11) U95.C10(VOUT2_12) U95.C11(VOUT2_13) U95.C12(VOUT2_14) ; also on sheet 8 10 16 22 28 32 34 36 37 38 48 49 50 51 52 53 54 58
3V3_STBY_PG: R526.1 R869.2 U95.G8(PGOOD2) U95.G9(PGOOD1) ; also on sheet 58
3V3_SYS: C688.1 Q18.1 Q18.2 Q18.3 R417.2 ; also on sheet 29 30 31 32 34 35 36 37
3V3_SYS_PG: R525.2 R527.1 U60.1(GDR)
5V0_PG: U95.F5(RUN1) U95.F9(RUN2) ; also on sheet 58
12V_AUX: C607.2 C608.2 C615.1 C616.1 C617.1 C618.1 C619.1 C620.1 D15.1(C) J11.1(12V) J11.2(12V) J11.3(12V) R464.1 R472.1 U54.9(VIN1) U54.10(VIN2) U54.11(VIN3) U54.12(VIN4)
12V_AUX_IN: C625.1 C626.1 C629.2 C692.1 C695.1 D16.5(C) Q16.1(S1) Q16.2(S2) Q16.3(S3) R468.1 R531.1 U53.2(SRC) U53.4(IN) U54.5(VOUT1) U54.6(VOUT2) U54.7(VOUT3) U54.8(VOUT4) ; also on sheet 10 43 44 45 46 58
12V_PCIE_HSC: C602.1 C603.1 C606.2 D14.5(C) U50.5(VOUT1) U50.6(VOUT2) U50.7(VOUT3) U50.8(VOUT4) U51.1(S1) U51.2(S2) U51.3(S3) U52.2(IN)
12V_PCIE_IN: C614.1 C1115.1 C1116.1 C1117.1 C1118.1 C1120.2 C1121.2 C1122.1 Q16.5(D1) R1005.1 U51.5(D) U52.1(OUT) U52.6(VDD) U53.8(OUT) U95.J2(VIN21) U95.J3(VIN22) U95.J4(VIN23) U95.J9(VIN24) U95.J10(VIN25) U95.J11(VIN26) U95.K2(VIN27) U95.K3(VIN28) U95.K4(VIN29) U95.K9(VIN30) U95.K10(VIN31) U95.K11(VIN32) U95.L2(VIN11) U95.L3(VIN12) U95.L4(VIN13) U95.L5(VIN14) U95.L6(VIN15) U95.L7(VIN16) U95.L8(VIN17) U95.L9(VIN18) U95.L10(VIN19) U95.L11(VIN20) U95.M2(VIN1) U95.M3(VIN2) U95.M4(VIN3) U95.M5(VIN4) U95.M6(VIN5) U95.M7(VIN6) U95.M8(VIN7) U95.M9(VIN8) U95.M10(VIN9) U95.M11(VIN10) ; also on sheet 28 47 49 50 55 56
GND: C592.2 C593.2 C594.2 C595.2 C596.2 C597.2 C598.2 C599.1 C600.2 C601.2 C603.2 C604.2 C605.2 C607.1 C608.1 C609.2 C615.2 C616.2 C617.2 C618.2 C619.2 C620.2 C621.1 C622.2 C623.2 C624.2 C626.2 C627.2 C628.2 C688.2 C689.1 C690.1 C692.2 C693.2 C695.2 C1105.1 C1106.1 C1107.1 C1110.1 C1111.1 C1112.1 C1115.2 C1116.2 C1117.2 C1118.2 C1120.1 C1121.1 C1122.2 C1123.1 C1218.2 D13.2 D14.1(A1) D14.2(A2) D14.3(A3) D14.4(A4) D15.2 D16.1(A1) D16.2(A2) D16.3(A3) D16.4(A4) J11.4(SENSE1) J11.5(GND) J11.6(SENSE0) J11.7(GND) J11.8(GND) J12.2 J13.2(GND) Q17.2(SOURCE) R417.1 R458.2 R459.2 R461.1 R462.1 R463.2 R465.2 R470.1 R475.2 R476.2 R477.1 R479.1 R480.2 R524.1 R541.1 R6879.2 ST7.1 ST31.2 U50.13(GND) U52.4(GND) U52.7(EP_GND) U54.13(GND) U60.2(GND) U95.A6(GND1) U95.A7(GND2) U95.B6(GND3) U95.B7(GND4) U95.D1(GND5) U95.D2(GND6) U95.D3(GND7) U95.D4(GND8) U95.D9(GND9) U95.D10(GND10) U95.D11(GND11) U95.D12(GND12) U95.E1(GND13) U95.E2(GND14) U95.E3(GND15) U95.E4(GND16) U95.E10(GND17) U95.E11(GND18) U95.E12(GND19) U95.F1(GND20) U95.F2(GND21) U95.F3(GND22) U95.F10(GND23) U95.F11(GND24) U95.F12(GND25) U95.G1(GND26) U95.G3(GND27) U95.G10(GND28) U95.G12(GND29) U95.H1(GND30) U95.H2(GND31) U95.H3(GND32) U95.H4(GND33) U95.H5(GND34) U95.H6(GND35) U95.H7(GND36) U95.H9(GND37) U95.H10(GND38) U95.H11(GND39) U95.H12(GND40) U95.J1(GND41) U95.J5(GND42) U95.J8(GND43) U95.J12(GND44) U95.K1(GND45) U95.K5(GND46) U95.K6(GND47) U95.K7(GND48) U95.K8(GND49) U95.K12(GND50) U95.L1(GND51) U95.L12(GND52) U95.M1(GND53) U95.M12(GND54) ; also on sheet 8 9 10 11 12 13 15 16 19 20 21 22 23 24 25 26 27 28 29 30 31 32 33 34 35 36 37 38 39 43 44 45 46 47 48 49 50 51 52 53 54 55 56 58
ASEL0: R550.1 U61.23(ASEL0)
ASEL1: R551.1 U61.24(ASEL1)
AUX_HSC_ALERT_N: R478.1 U54.15(SMB_ALERTB) ; also on sheet 10
AUX_HSC_BST: C625.2 U54.4(VBST)
AUX_HSC_FAULTB: R474.2 U54.16(FAULTB)
AUX_HSC_ILOAD: C627.1 R480.1 U54.2(ILOAD)
AUX_HSC_PG: R471.2 U54.17(PWRGD) ; also on sheet 10
AUX_HSC_ROCP: R479.2 U54.18(ROCP)
AUX_HSC_SMB_ID_R: R477.2 U54.20(SMB_ID)
AUX_HSC_SS: C628.1 C629.1 U54.3(SS)
AUX_VDD_1V85: C621.2 C622.1 R474.1 U54.22(VDD)
EN_G0: R528.1 ; also on sheet 10
EN_G1: R535.2 R542.2 U61.20(RUN0) ; also on sheet 10 43 44 45 46 47 48 49
FPGA_3V3_SVID_SCL: R530.1 R539.1 R6907.2 U61.15(SCL) ; also on sheet 35
FPGA_3V3_SVID_SDA: R529.1 R538.1 R6906.2 U61.16(SDA) ; also on sheet 35
FPGA_GNDSENSE: R534.1 ; also on sheet 23
FPGA_VCC: R532.2 ; also on sheet 23 39 43 44 45 46
FPGA_VCC_GND: C691.2 C694.2 C697.2 C698.2 C699.2 C700.2 C1219.2 R547.2 R550.2 R551.2 R552.2 R553.2 R554.1 R555.1 R557.1 R558.1 ST7.2 U61.53(GND) ; also on sheet 43 44 45 46
FPGA_VCC_HSSI_GNDSENSE: C701.1 U61.41(VSENSE1-) ; also on sheet 47
FPGA_VCC_HSSI_GXF_PG: R564.2 U61.36(PGOOD1) ; also on sheet 49
FPGA_VCC_HSSI_SENSE: C701.2 U61.40(VSENSE1+) ; also on sheet 47
FPGA_VCC_PG: R563.2 U61.11(PGOOD0/CLKOUT) ; also on sheet 49
FPGA_VCCLSENSE: R533.1 ; also on sheet 23
IREF: C1219.1 R543.2 R544.1 R545.1 R546.1 R547.1 U61.33(IREF) ; also on sheet 43 44 45 46 47
ISENSE0: U61.4(ISENSE0) ; also on sheet 43
ISENSE1: U61.43(ISENSE1) ; also on sheet 47
ISENSE2: U61.3(ISENSE2) ; also on sheet 44
ISENSE3: U61.52(ISENSE3) ; also on sheet 45
ISENSE4: U61.51(ISENSE4) ; also on sheet 46
LT_3V3_SCK: R559.2 ; also on sheet 34
LT_3V3_SCSn: R565.2 ; also on sheet 34
LT_3V3_SDI: R556.2 ; also on sheet 34
LT_3V3_SPI_ERRn: R561.2 ; also on sheet 34
LT_SVID_SCL: J13.3(SCL) R530.2
LT_SVID_SDA: J13.1(SDA) R529.2
LTC_FAULT_N: R560.2 U61.18(FAULT0b) U61.19(FAULT1b) ; also on sheet 10
LTC_INTVCC: C690.2 U61.31(INTVCC)
LTC_SYNC: R540.2 U61.14(SYNC)
LTC_VDD25: C691.1 U61.28(VDD25)
LTC_VDD33: C694.1 D17.1(C) R535.1 R536.1 R537.2 R538.2 R539.2 R540.1 R543.1 R560.1 R562.1 R563.1 R564.1 R566.1 U61.30(VDD33)
MAX_I2C_SCL: J12.1 R473.1 R6907.1 U50.1(SMB_CLK) U54.1(SMB_CLK) ; also on sheet 8 10 32 33 34 37 49 50
MAX_I2C_SDA: J12.3 R6906.1 U50.19(SMB_DATA) U54.19(SMB_DATA) ; also on sheet 8 10 32 33 34 37 49 50
PCIE_EP_12V: C592.1 C593.1 C594.1 C595.1 C596.1 C597.1 C598.1 D13.1(C) R456.1 R466.1 U50.9(VIN1) U50.10(VIN2) U50.11(VIN3) U50.12(VIN4) ; also on sheet 8
PCIE_HSC_ALERT_N: R460.1 U50.15(SMB_ALERTB) ; also on sheet 10
PCIE_HSC_BST: C602.2 U50.4(VBST)
PCIE_HSC_EN: C601.1 R456.2 R458.1 R469.2 U50.14(EN/UVLO)
PCIE_HSC_FAULTB: R457.2 U50.16(FAULTB)
PCIE_HSC_ILOAD: C604.1 R463.1 U50.2(ILOAD)
PCIE_HSC_PG: R455.2 U50.17(PWRGD) ; also on sheet 10
PCIE_HSC_ROCP: R462.2 U50.18(ROCP)
PCIE_HSC_SMB_ID_R: R461.2 U50.20(SMB_ID)
PCIE_HSC_SS: C605.1 C606.1 U50.3(SS)
PCIE_VDD_1V85: C599.2 C600.1 R457.1 U50.22(VDD)
POWER_ON: C623.1 R465.1 R472.2 R475.1 SW5.5 U54.14(EN/UVLO)
PWM0: U61.5(PWM0) ; also on sheet 43
PWM1: U61.42(PWM1) ; also on sheet 47
PWM2: U61.2(PWM2) ; also on sheet 44
PWM3: U61.1(PWM3) ; also on sheet 45
PWM4: U61.50(PWM4) ; also on sheet 46
PWRGD_G0: R523.2 R526.2 R527.2 ; also on sheet 10
SHARE_CLK: R537.1 U61.29(SHARE_CLK)
TSNS0: R548.2 ; also on sheet 43 44 45 46
TSNS1: R549.2 ; also on sheet 47
VOUT0_CFG: R552.1 U61.25(VOUT0_CFG)
VOUT1_CFG: R553.1 U61.26(VOUT1_CFG)
VSENSE0+: C696.2 R532.1 R533.2 U61.7(VSENSE0+)
VSENSE0-: C696.1 R534.2 R541.2 U61.6(VSENSE0-)
N1229237: U51.4(G) U52.3(GATE)
N1229245: R459.1 U50.21(ILOAD_IN)
N1234667: Q16.4(G) R467.1
N1234809: C609.1 R467.2 U53.1(GATE)
N1235245: Q17.3(DRAIN) R468.2 U53.5(~{SHDN})
N1235299: C614.2 R470.2 U53.6(VSS)
N1235337: Q17.1(GATE) R469.1
N1235973: R476.1 U54.21(ILOAD_IN)
N1428757: C689.2 Q18.4 U60.4(GATE)
N1428777: R522.1 R524.2 R528.2 U60.3(~{SHDN})
N1987677: R546.2 U61.44(ISENSE7)
N1989130: R544.2 U61.48(ISENSE5)
N1989134: R545.2 U61.47(ISENSE6)
N1993333: C693.1 R531.2 U61.32(VIN)
N1995084: R542.1 U61.21(RUN1)
N1995190: R548.1 U61.8(TSNS0)
N1995248: R554.2 U61.22(RSET)
N1995256: R555.2 U61.27(PWM_CFG)
N1995356: R556.1 R558.2 U61.12(SDI)
N1995388: R557.2 R559.1 U61.13(SCK)
N1995426: R561.1 R562.2 U61.34(SERRb)
N1995468: R565.1 R566.2 U61.35(SCSb)
N1997388: C697.1 U61.10(ITH_R0)
N1997392: C699.1 U61.9(ITH0)
N2007530: R549.1 U61.39(TSNS1)
N2089040: R536.2 U61.17(ALERTb)
N2530657: C698.1 U61.37(ITH_R1)
N2530661: C700.1 U61.38(ITH1)
N2608710: D17.2 J13.4(3.4V)
N2760104: R464.2 SW5.4
N2760122: R466.2 SW5.6
N3089983: C624.1 R473.2
N6362776: C1123.2 R869.1 U95.H8(INTVCC)
N6365028: C1125.1 C1126.2 R1004.2 U95.D5(VFB1) U95.D7(VFB2)
N6365040: U95.E6(COMP1) U95.E7(COMP2)
N6365052: C1124.2 U95.D8(TRACK2) U95.E5(TRACK1)
N6365353: C1126.1 ST32.1 U95.E8(DIFFP)
N6365365: ST33.1 U95.E9(DIFFN)
N6366094: R6879.1 ST33.2
N6366537: R6878.1 ST32.2
N6366923: C1125.2 U95.C5(VOUTS1) U95.F8(DIFFOUT)
N6369590: R6880.2 U95.C6(FSET)
N6369792: R1005.2 U95.J6(TEMP)
N7012506: C1218.1 U95.J7(EXTVCC)

Not connected (* = marked no-connect by the designer): SW5 1* 2* 3*; U52 5(NC)*; U53 3(NC1)* 7(NC2)*; U61 45(PWM7)* 46(PWM6)* 49(PWM5)*; U95 C8(VOUTS2)* G2(SW1)* G4(PHASMD)* G5(CLKOUT)* G11(SW2)*

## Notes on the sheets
sheet 40
- VDD = 1.76V / 1.85V / 1.94V
- 12V_PCIE = 75W = 12V @ 6.25A
- H = 1.0mm
  Place on bottom side
- Rdson = 1.9mOhm for MAX16550
  Rdson = 0.95mOhm for MAX16545B
  Internal FET Ploss Max = 668mW
- Place close to
  MAX16550 VIN pin
- 25V, 40A, 3.5mOhm
- POWER_ON = 2.37V
- VIN = 10.8V / 12V / 13.2V
- When 16V,   EN = 1.96V
  When 15V,   EN = 1.84V
  When 14V,   EN = 1.72V
  When 13V,   EN = 1.59V
  When 12V,   EN = 1.47V
  When 11V,   EN = 1.35V
  When 10V,   EN = 1.23V
- VIN absmax = 16V
- ENth = 0.95V / 1V / 1.05V
- EN ABSMAX = 2.5V
- pull-ups on pg35
- Cboost
- Absmax = 6V
  Vih = 1.2V
  Vil = 0.8V
- H = 1.1mm
  Place on bottom side
- Ideal Diode
- I2C:
  AbsMax = 6V
  Vih_min = 2.1V
  Vil_max = 0.8V
- 20.6A = 1.34745V
- MIN:  16.18A, 194W
  TYP:  18.39A, 220.68W
  MAX:  20.6A, 247.2W
- ILoad = 5uA / A
- Viload = 1.35V
  Absmax = 2.5V
- Rocp
- R_Iload
- ADDR = 42h
- Tr = 6mS
- 12V_PCIE Hot Swap Controller
- Power On Switch
- Vgs(th) = 2.5V/3.7V/4.5V
- (AUX Power)
- ON
- Optional for EMC testing
- 2.37V
- (Slot Power)
- OFF
- 150W 2x4 ATX AUX
  INPUT POWER
  CONNECTOR
- -When 12V PCIE slot power and 12V AUX power is provided
  (Add-in Card Mode), ON switch has no function.
  -When No 12V PCIE slot power is available (Bench Mode), ON
  switch is used to power the board on/off.
- Vshdn_absmax = 100V
- Vshdn_th = 0.6V/1.2V/2V
- VGS(th) max = 0.85V
- VDD = 1.76V / 1.85V / 1.94V
- 12V_PCIE = 150W = 12V @ 12.5A
- Place close to
  MAX16550 VIN pin
- Rdson = 1.9mOhm for MAX16550
  Rdson = 0.95mOhm for MAX16545B
  Internal FET Ploss Max = 668mW
- 12V_AUX_IN C_load ~ 1472uF
- When 16V,   EN = 1.96V
  When 15V,   EN = 1.84V
  When 14V,   EN = 1.72V
  When 13V,   EN = 1.59V
  When 12V,   EN = 1.47V
  When 11V,   EN = 1.35V
  When 10V,   EN = 1.23V
- VIN = 10.8V / 12V / 13.2V
- VIN absmax = 16V
- ENth = 0.95V / 1V / 1.05V
- EN ABSMAX = 2.5V
- Pull-ups on PG35
- Cboost
- Pull-ups on PG35
- Absmax = 6V
  Vih = 1.2V
  Vil = 0.8V
- I2C:
  AbsMax = 6V
  Vih_min = 2.1V
  Vil_max = 0.8V
- I2C ACCESS HEADER
  Do not place on END of daisy chain
- 20.6A = 1.34745V
- MIN:  16.18A, 194W
  TYP:  18.39A, 220.68W
  MAX:  20.6A, 247.2W
- ILoad = 5uA / A
- Viload = 1.35V
  Absmax = 2.5V
- Rocp
- R_Iload
- ADDR = 40h
- Tr = 6mS
- 12V_AUX Hot Swap Controller
sheet 41
- 3.3V +/-5%
- PVIN = 4.5V to 16V, Absmax = 18V
- Pull-up on pg44
- Vth = 1.1V/1.25V/1.40V
  Absmax = 6V
- TSS = 2.3mS
- 750KHz
- 90deg
- AGND
- PGND
- PLACE Output decoupling caps
  close to the device.  Connect
  AGND and PGND at the point of
  cap GND connection.
- Route as diff pair. Remote sense
  at furthest 3.3V location
- VGS = 3.6Vmin, Rds(on) = 1.5mOhm
  Power @ 20A = 0.6Wmax
- VGATE = 6.9V/7.25V/7.5V
- PG when Vout > VCC-0.7V (2.6V)
- SHDNth = 0.4V / 1.6V
  ABSmax = 7.5V
- SOT-23
sheet 42
- LTC Programming Header
- SHARE VID I2C with MAX10 TELEMETRY I2C
- Pull-ups on PG35
- Pull-ups on PG35
- Agilex supports Multi-master
- 5.2V
- Place close
  to FPGA
- 28mA
- Place close to
  LTC3888 in layout
- Remote sense to FPGA
  Diff pair routing
- Pull-ups on PG35
- Place close to
  LTC3888 in layout
- Vout = 0.80V at startup
- 18.7K is required in datasheet
- I2C Addr:  55H
- 4+2
  500KHz
- Remote sense to FPGA
  Diff pair routing
- Pullup on pg10 to 3V3_STBY
- Pullups on pg53
